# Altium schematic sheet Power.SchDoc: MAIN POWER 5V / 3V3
size A4; Date: Not used; ApprovedBy: Not used; CheckedBy: Not used; Author: Not used; CompanyName: STMicroelectronics; DrawnBy: Not used; Engineer: Not used; Organization: Not used; Address1: Not used; Address2: Not used; Address3: Not used; Address4: Not used; DocumentNumber: 6; Revision: Not used; SheetNumber: 6; SheetTotal: 8
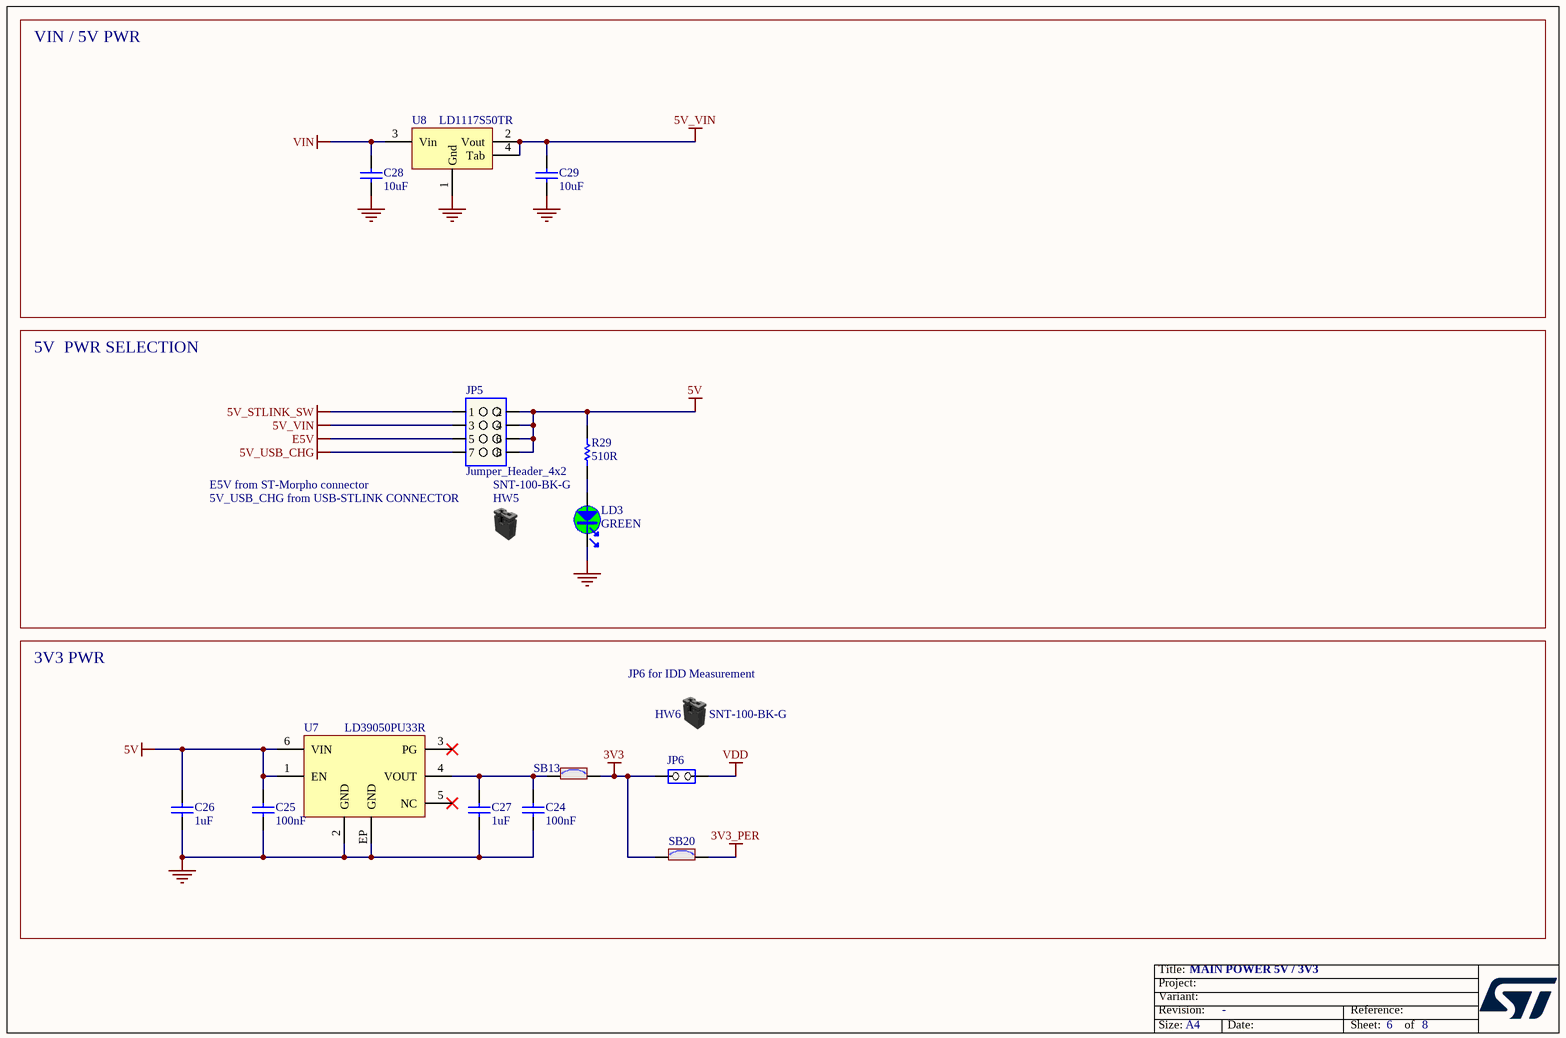
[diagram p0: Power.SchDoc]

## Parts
C24  value 100nF  [C0603]  (hidden comment: Capacitor)
C25  value 100nF  [C0603]  (hidden comment: Capacitor)
C26  value 1uF  [C0603]  (hidden comment: Capacitor)
C27  value 1uF  [C0603]  (hidden comment: Capacitor)
C28  value 10uF  [C0805]  (hidden comment: Capacitor)
C29  value 10uF  [C0805]  (hidden comment: Capacitor)
HW5  value SNT-100-BK-G  (hidden comment: Shunt Black 2.54mm)  (mechanical)
HW6  value SNT-100-BK-G  (hidden comment: Shunt Black 2.54mm)  (mechanical)
JP5  value Jumper_Header_4x2  [CON_SAMTEC_TSW-104-07-X-D]  (hidden comment: Jumper_Header 4x2)
JP6  Jumper_Header 2x1  [CON_SAMTEC_TSW-102-07-G-S]  (value not drawn)
LD3  value GREEN  [LED_0603_GREEN]  (hidden comment: LED_green)
R29  value 510R  [R0603]  (hidden comment: Resistor)
SB13  SB_ON  [SOLDER-BRIDGE_R0603-0R]  (value not drawn)
SB20  SB_ON  [SOLDER-BRIDGE_R0603-0R]  (value not drawn)
U7  LD39050PU33R  [ICC_DFN6-EPAD_3X3_P095]
U8  LD1117S50TR  [REG_SOT223-TAB]

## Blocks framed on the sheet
VIN / 5V PWR: C28 C29 U8
5V  PWR SELECTION: HW5 JP5 LD3 R29
3V3 PWR: C24-C27 HW6 JP6 SB13 SB20 U7

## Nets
3V3: JP6.1(COMMON) SB13.2 SB20.1
3V3_PER: SB20.2
5V: C25.2 C26.2 JP5.2 JP5.4 JP5.6 JP5.8 R29.2 U7.1(EN) U7.6(VIN)
5V_STLINK_SW: JP5.1
5V_USB_CHG: JP5.7
5V_VIN: C29.2 JP5.3 U8.2(Vout) U8.4(Tab)
E5V: JP5.5
GND: C24.1 C25.1 C26.1 C27.1 C28.1 C29.1 LD3.2 U7.2(GND) U7.EP(GND) U8.1(Gnd)
VDD: JP6.2(NO)
VIN: C28.2 U8.3(Vin)
NetC24_2: C24.2 C27.2 SB13.1 U7.4(VOUT)
NetLD3_1: LD3.1 R29.1

Not connected (* = marked no-connect by the designer): U7 3(PG)* 5(NC)*

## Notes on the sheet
- E5V from ST-Morpho connector
- 5V_USB_CHG from USB-STLINK CONNECTOR
- (near HW6) JP6 for IDD Measurement

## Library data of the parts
C24 C25 = MCD-00237: Capacitor, MLCC, 100nF, 6V3, X5R, +/-10%, 0603, T=0.8mm; Part_Preference: Not recommended; Manufacturer: YAGEO; Manufacturer_Part_Number: CC0603KRX5R5BB104; Component_Country_Of_Origin: China; ShowFields: YES; ID: 2631
C26 C27 = MCD-00238: Capacitor, MLCC, 1uF, 6V3, X5R, +/-10%, 0603, T=0,8mm; Manufacturer_Part_Number: CC0603KRX5R5BB105; Manufacturer: YAGEO; Part_Preference: Recommended
C28 C29 = MCD-00014: Capacitor, MLCC, 10uF, 25V, X5R, +/-10%, 0805, T=0,85mm; Manufacturer_Part_Number: CC0805KRX5R8BB106; Manufacturer: YAGEO; Part_Preference: Recommended
HW5 HW6 = MCD-00043: SHUNT 2.54mm BLACK; Manufacturer: SAMTEC; Part_Type: Misc; Part_Preference: Recommended; Alternate_Manufacturer: JIUBABA; Alternate_Manufacturer_Part_Number: 316102S111A
JP5 = MCD-00633: Header, 4x2, 2,54mm, VR, TH, Height 5.84mm/2.54mm; Part_Type: Connector; Manufacturer_Part_Number: TSW-104-07-G-D; Manufacturer: SAMTEC; Part_Preference: Recommended
JP6 = MCD-00045: Header, 2x1, 2,54mm, VR, TH, Height 5.84mm/2.54mm; Manufacturer_Part_Number: TSW-102-07-G-S; Manufacturer: SAMTEC; Part_Type: Connector; Part_Preference: Recommended; Alternate_Manufacturer: JIUBABA; LIANYI; Alternate_Manufacturer_Part_Number: 313102S111116;313102S111116; Value: Shunt not fitted
LD3 = MCD-02900: LED, Green, 2V, 25mA, 0603, SMD; Part_Type: Display; Part_Preference: Recommended; Manufacturer: EVERLIGHT; Manufacturer_Part_Number: 19-213SYGC/S530-E2/5T; Full_Alternate_Internal_Part_Number: MCD-00320; Partial_Alternate_Internal_Part_Number: MCD-00050; Component_Country_Of_Origin: China; ShowFields: YES; ID: 5016
R29 = MCD-00225: Resistor,510R,0603,1%,1/10W; Manufacturer_Part_Number: RC0603FR-07510RL; Manufacturer: YAGEO; Part_Preference: Recommended
SB13 SB20 = MCD-00071: Solder Bridge ON; Part_Type: Misc; Part_Preference: Recommended; Manufacturer: YAGEO; Manufacturer_Part_Number: RC0603JR-070RL
U7 = MCD-00215: Low quiescent current and low noise voltage regulators; Manufacturer: STMICROELECTRONICS; Part_Type: IC; BMS_Part_Number: 9176126; Part_Preference: Recommended; Manufacturer_HQ_COO: EU
U8 = MCD-00088: IC REG LDO 5V 0.8A SOT223; Manufacturer: STMICROELECTRONICS; BMS_Part_Number: 9176133; Part_Preference: Recommended; Manufacturer_HQ_COO: EU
